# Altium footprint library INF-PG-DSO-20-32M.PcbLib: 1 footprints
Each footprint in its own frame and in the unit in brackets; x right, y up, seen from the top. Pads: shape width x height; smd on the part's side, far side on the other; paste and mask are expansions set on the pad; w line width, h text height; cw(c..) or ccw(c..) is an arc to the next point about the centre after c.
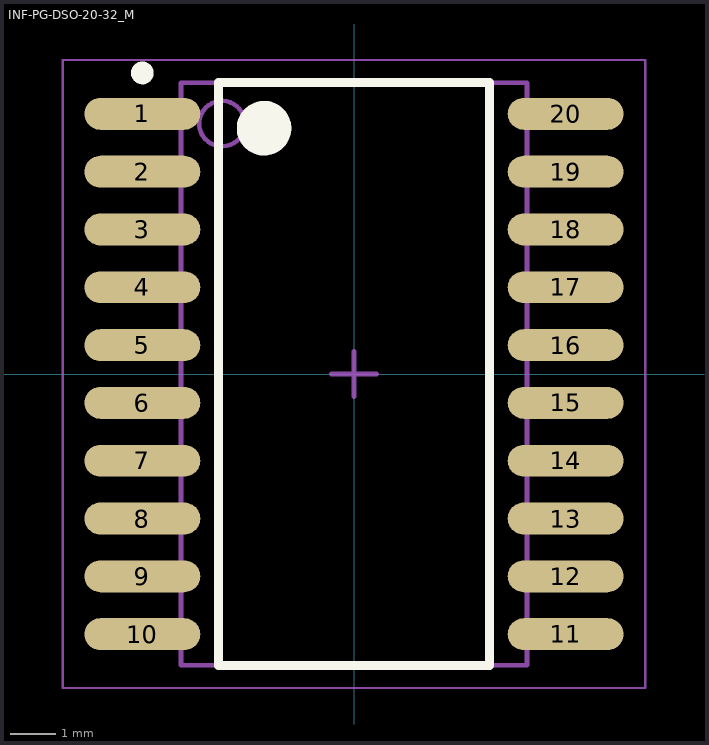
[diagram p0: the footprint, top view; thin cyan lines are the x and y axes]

## INF-PG-DSO-20-32_M [mm] "SOP, 20-Leads, Body 12.7x7.5mm, Pitch 1.27mm, IPC Low Density"
height 2.65
pads (20):
  oval 2.55x0.7 smd: 1(-4.65,5.715) 2(-4.65,4.445) 3(-4.65,3.175) 4(-4.65,1.905) 5(-4.65,0.635) 6(-4.65,-0.635) 7(-4.65,-1.905) 8(-4.65,-3.175) 9(-4.65,-4.445) 10(-4.65,-5.715) 11(4.65,-5.715) 12(4.65,-4.445) 13(4.65,-3.175) 14(4.65,-1.905) 15(4.65,-0.635) 16(4.65,0.635) 17(4.65,1.905) 18(4.65,3.175) 19(4.65,4.445) 20(4.65,5.715)
Top Overlay:
  circle w0.25: c-4.65,6.615 r0.125
  circle w0.6: c-1.975,5.4 r0.3
  lines w0.2: -2.975,-6.4 -2.975,6.4 2.975,6.4 2.975,-6.4 -2.975,-6.4
Mechanical 13:
  circle w0.1: c-2.9,5.5 r0.5
  lines w0.1: -3.8,-6.4 -3.8,6.4 3.8,6.4 3.8,-6.4 -3.8,-6.4
Mechanical 15:
  lines w0.05: -6.4,-6.9 -6.4,6.9 6.4,6.9 6.4,-6.9 -6.4,-6.9
  lines w0.1: -0.5,0 0.5,0 ; 0,-0.5 0,0.5
3D body: height 2.65, standoff 0.1, extent -3.8,-6.4 3.8,6.4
